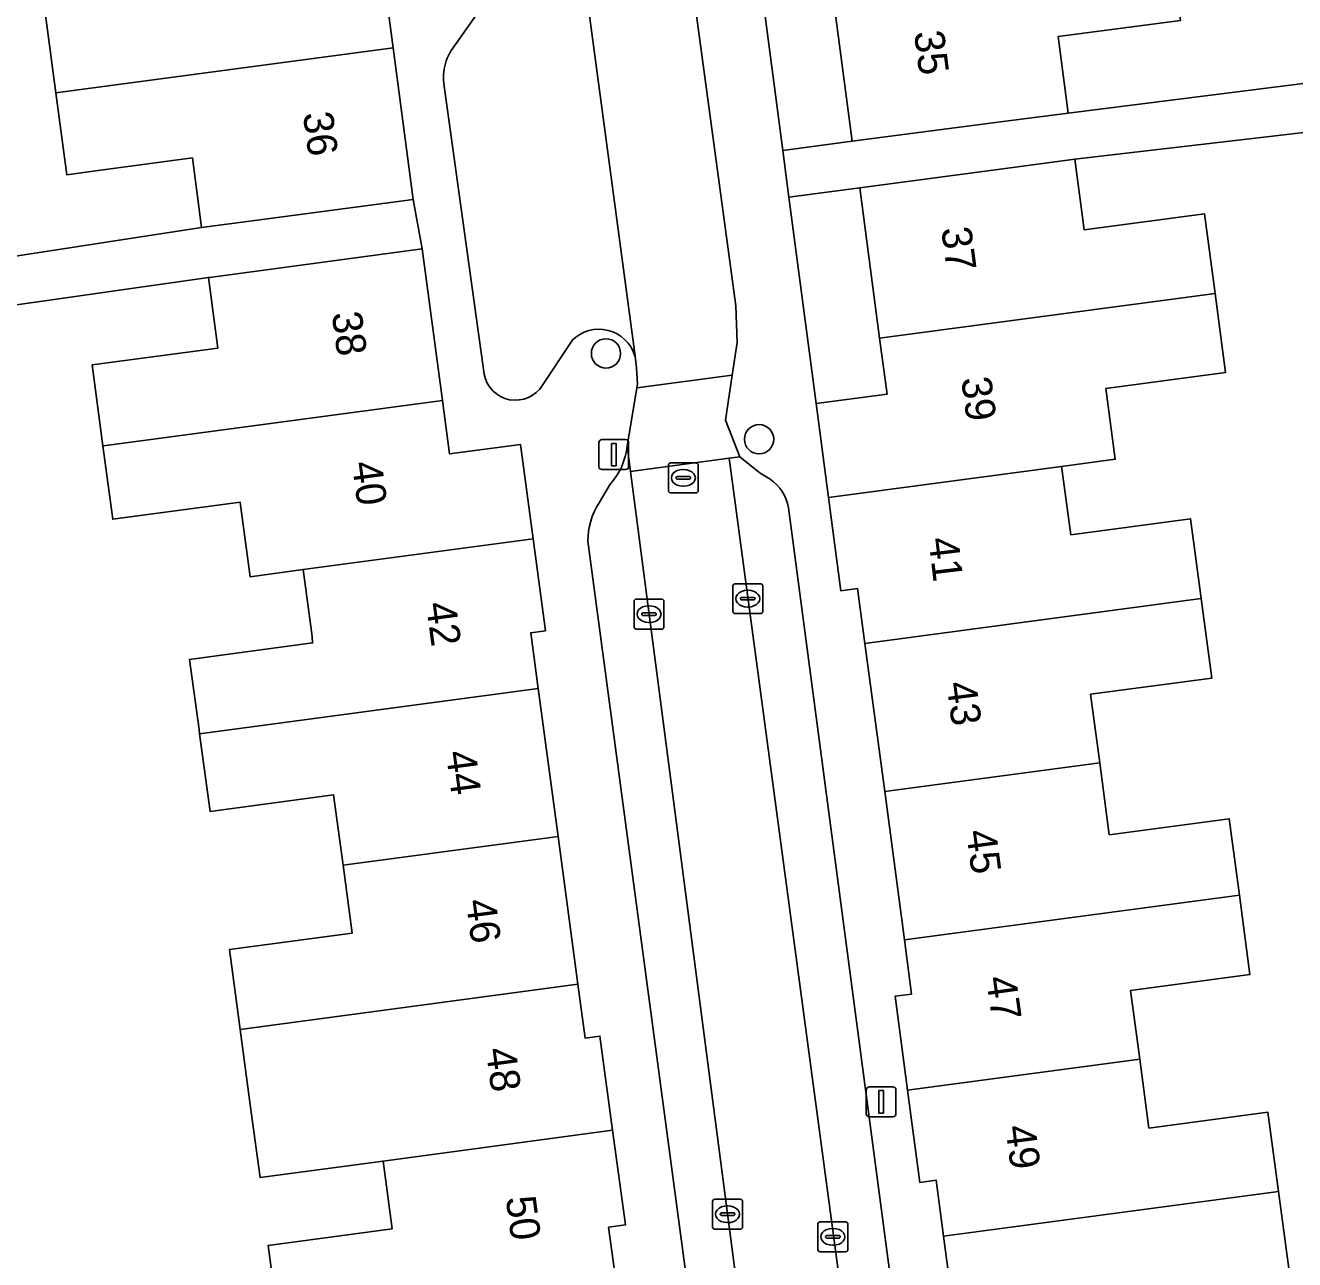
# Model space of a CAD drawing. Extents: x 163147 to 163550, y 380933 to 381639.
# Drawn here: x 163317.26 to 163359.68, y 381332.22 to 381373.46 of the extents above; entities that cross this region are included whole.
import ezdxf

# ---------------------------------------------------------------- set-up
doc = ezdxf.new("R2010")
doc.units = 0
for name, color, linetype in [('IMGEO_Boom', 7, 'Continuous'), ('IMGEO_Erf', 7, 'Continuous'), ('IMGEO_Kolk', 7, 'Continuous'), ('IMGEO_Lichtmast', 7, 'Continuous'), ('IMGEO_Pand', 7, 'Continuous'), ('IMGEO_Pand_nummerreeks', 7, 'Continuous'), ('IMGEO_Parkeervlak_open', 7, 'Continuous'), ('IMGEO_Rijbaan_lokaal_open', 7, 'Continuous'), ('IMGEO_Rioolput', 7, 'Continuous'), ('IMGEO_Voetpad_open', 7, 'Continuous')]:
    doc.layers.add(name, color=color, linetype=linetype)

msp = doc.modelspace()

# ---------------------------------------------------------------- linework, layer by layer
at = {"layer": 'IMGEO_Boom'}
for centre in [(163336.666, 381362.496), (163341.784, 381359.63)]:
    msp.add_circle(centre, 0.489, dxfattribs=at)
at = {"layer": 'IMGEO_Erf'}
for points in [[(163341.643, 381394.54), (163340.996, 381399.507), (163340.35, 381404.474), (163339.703, 381409.442), (163339.057, 381414.409), (163338.425, 381419.264), (163336.029, 381419.012), (163342.573, 381369.282), (163344.89, 381369.587), (163344.228, 381374.671), (163343.582, 381379.638), (163342.936, 381384.606), (163342.289, 381389.573)], [(163345.144, 381368.026), (163342.779, 381367.715), (163343.686, 381360.824), (163346.061, 381361.14), (163345.812, 381363.011)]]:
    msp.add_lwpolyline(points, close=True, dxfattribs=at)
for points in [[(163303.373, 381374.262), (163303.542, 381373.013), (163306.346, 381373.386), (163306.845, 381369.687), (163307.335, 381366.064), (163304.531, 381365.686), (163304.775, 381363.875), (163323.147, 381366.702), (163322.843, 381369.028), (163319.523, 381368.586), (163318.645, 381368.469), (163318.281, 381371.208), (163317.936, 381373.801)], [(163355.862, 381373.616), (163351.776, 381373.084), (163352.109, 381370.526), (163370.824, 381372.885)], [(163370.998, 381371.159), (163352.337, 381368.984), (163352.651, 381366.625), (163356.669, 381367.16), (163357.022, 381364.504), (163357.374, 381361.862), (163353.373, 381361.329), (163353.688, 381358.964), (163351.894, 381358.725), (163351.926, 381358.487), (163352.198, 381356.441), (163356.204, 381356.974), (163356.559, 381354.306), (163356.912, 381351.652), (163352.862, 381351.112), (163353.168, 381348.815), (163353.487, 381346.417), (163357.495, 381346.95), (163357.835, 381344.397), (163358.188, 381341.743), (163354.197, 381341.212), (163354.503, 381338.914), (163354.809, 381336.616), (163358.79, 381337.146), (163359.143, 381334.492), (163359.485, 381331.923)], [(163325.732, 381330.017), (163325.372, 381332.695), (163329.518, 381333.252), (163329.214, 381335.515), (163325.105, 381334.964), (163324.811, 381337.152), (163324.441, 381339.905), (163324.082, 381342.578), (163328.184, 381343.129), (163327.879, 381345.396), (163327.563, 381347.75), (163323.433, 381347.195), (163323.086, 381349.783), (163323.065, 381349.936), (163322.751, 381352.275), (163326.859, 381352.826), (163326.841, 381353.035), (163326.54, 381355.275), (163324.772, 381355.038), (163324.438, 381357.519), (163324.437, 381357.528), (163320.182, 381356.957), (163319.853, 381359.407), (163319.49, 381362.112), (163323.698, 381362.677), (163323.382, 381365.033), (163307.81, 381362.818)]]:
    msp.add_lwpolyline(points, dxfattribs=at)
at = {"layer": 'IMGEO_Kolk'}
for p, q in [((163340.905, 381353.878), (163340.905, 381354.73)), ((163340.98, 381354.804), (163341.832, 381354.804)), ((163341.393, 381354.584), (163341.418, 381354.584)), ((163341.906, 381354.73), (163341.906, 381353.878)), ((163337.603, 381353.362), (163337.603, 381354.214)), ((163337.678, 381354.288), (163338.53, 381354.288)), ((163338.091, 381354.068), (163338.116, 381354.068)), ((163338.604, 381354.214), (163338.604, 381353.362)), ((163341.164, 381354.298), (163341.164, 381354.31)), ((163341.602, 381354.261), (163341.204, 381354.261)), ((163341.207, 381354.347), (163341.605, 381354.347)), ((163341.648, 381354.31), (163341.648, 381354.298)), ((163337.862, 381353.782), (163337.862, 381353.794)), ((163338.3, 381353.745), (163337.902, 381353.745)), ((163337.905, 381353.831), (163338.303, 381353.831)), ((163338.346, 381353.794), (163338.346, 381353.782)), ((163341.832, 381353.804), (163340.98, 381353.804)), ((163341.416, 381354.024), (163341.391, 381354.024)), ((163338.53, 381353.288), (163337.678, 381353.288)), ((163338.114, 381353.508), (163338.089, 381353.508)), ((163340.228, 381333.311), (163340.228, 381334.163)), ((163340.303, 381334.237), (163341.155, 381334.237)), ((163341.229, 381334.163), (163341.229, 381333.311)), ((163340.487, 381333.731), (163340.487, 381333.743)), ((163340.925, 381333.694), (163340.527, 381333.694)), ((163340.53, 381333.78), (163340.928, 381333.78)), ((163340.716, 381334.017), (163340.741, 381334.017)), ((163340.971, 381333.743), (163340.971, 381333.731)), ((163340.739, 381333.457), (163340.714, 381333.457)), ((163343.748, 381332.556), (163343.748, 381333.408)), ((163343.823, 381333.482), (163344.675, 381333.482)), ((163344.749, 381333.408), (163344.749, 381332.556)), ((163341.155, 381333.237), (163340.303, 381333.237)), ((163344.007, 381332.976), (163344.007, 381332.988)), ((163344.445, 381332.939), (163344.047, 381332.939)), ((163344.05, 381333.025), (163344.448, 381333.025)), ((163344.236, 381333.262), (163344.261, 381333.262)), ((163344.491, 381332.988), (163344.491, 381332.976)), ((163344.675, 381332.482), (163343.823, 381332.482)), ((163344.259, 381332.702), (163344.234, 381332.702))]:
    msp.add_line(p, q, dxfattribs=at)
for points in [[(163340.905, 381353.878), (163340.905, 381354.73)], [(163340.98, 381354.804), (163341.832, 381354.804)], [(163341.906, 381354.73), (163341.906, 381353.878)], [(163337.603, 381353.362), (163337.603, 381354.214)], [(163337.678, 381354.288), (163338.53, 381354.288)], [(163338.604, 381354.214), (163338.604, 381353.362)], [(163341.832, 381353.804), (163340.98, 381353.804)], [(163338.53, 381353.288), (163337.678, 381353.288)], [(163340.228, 381333.311), (163340.228, 381334.163)], [(163340.303, 381334.237), (163341.155, 381334.237)], [(163341.229, 381334.163), (163341.229, 381333.311)], [(163343.748, 381332.556), (163343.748, 381333.408)], [(163343.823, 381333.482), (163344.675, 381333.482)], [(163344.749, 381333.408), (163344.749, 381332.556)], [(163341.155, 381333.237), (163340.303, 381333.237)], [(163344.675, 381332.482), (163343.823, 381332.482)]]:
    msp.add_lwpolyline(points, dxfattribs=at)
for centre, radius, start, end in [((163340.982, 381354.728), 0.0765, 91.552, 178.448), ((163340.982, 381354.728), 0.0765, 91.552, 178.448), ((163341.83, 381354.728), 0.0765, 1.552, 88.448), ((163341.83, 381354.728), 0.0765, 1.552, 88.448), ((163337.68, 381354.212), 0.0765, 91.552, 178.448), ((163337.68, 381354.212), 0.0765, 91.552, 178.448), ((163338.528, 381354.212), 0.0765, 1.552, 88.448), ((163338.528, 381354.212), 0.0765, 1.552, 88.448), ((163341.204, 381354.307), 0.0403, 85.8775, 175.7526), ((163341.201, 381354.297), 0.0366, 178.938, 274.7102), ((163341.605, 381354.304), 0.043, 264.8664, 352.4533), ((163341.609, 381354.309), 0.0386, 1.7309, 96.639), ((163337.902, 381353.791), 0.0403, 85.8775, 175.7526), ((163337.899, 381353.781), 0.0366, 178.938, 274.7102), ((163338.303, 381353.788), 0.043, 264.8664, 352.4533), ((163338.307, 381353.793), 0.0386, 1.7309, 96.639), ((163340.982, 381353.88), 0.0765, 181.552, 268.448), ((163340.982, 381353.88), 0.0765, 181.552, 268.448), ((163341.83, 381353.88), 0.0765, 271.552, 358.448), ((163341.83, 381353.88), 0.0765, 271.552, 358.448), ((163337.68, 381353.364), 0.0765, 181.552, 268.448), ((163337.68, 381353.364), 0.0765, 181.552, 268.448), ((163338.528, 381353.364), 0.0765, 271.552, 358.448), ((163338.528, 381353.364), 0.0765, 271.552, 358.448), ((163340.305, 381334.161), 0.0765, 91.552, 178.448), ((163340.305, 381334.161), 0.0765, 91.552, 178.448), ((163341.153, 381334.161), 0.0765, 1.552, 88.448), ((163341.153, 381334.161), 0.0765, 1.552, 88.448), ((163340.527, 381333.74), 0.0403, 85.8775, 175.7526), ((163340.524, 381333.73), 0.0366, 178.938, 274.7102), ((163340.928, 381333.737), 0.043, 264.8664, 352.4533), ((163340.932, 381333.742), 0.0386, 1.7309, 96.639), ((163340.305, 381333.313), 0.0765, 181.552, 268.448), ((163340.305, 381333.313), 0.0765, 181.552, 268.448), ((163341.153, 381333.313), 0.0765, 271.552, 358.448), ((163341.153, 381333.313), 0.0765, 271.552, 358.448), ((163343.825, 381333.406), 0.0765, 91.552, 178.448), ((163343.825, 381333.406), 0.0765, 91.552, 178.448), ((163344.673, 381333.406), 0.0765, 1.552, 88.448), ((163344.673, 381333.406), 0.0765, 1.552, 88.448), ((163344.047, 381332.985), 0.0403, 85.8775, 175.7526), ((163344.044, 381332.975), 0.0366, 178.938, 274.7102), ((163344.448, 381332.982), 0.043, 264.8664, 352.4533), ((163344.452, 381332.987), 0.0386, 1.7309, 96.639), ((163343.825, 381332.558), 0.0765, 181.552, 268.448), ((163343.825, 381332.558), 0.0765, 181.552, 268.448), ((163344.673, 381332.558), 0.0765, 271.552, 358.448), ((163344.673, 381332.558), 0.0765, 271.552, 358.448)]:
    msp.add_arc(centre, radius, start, end, dxfattribs=at)
for centre, major_axis, ratio, start_param, end_param in [((163341.392, 381354.304), (-0.387, 0.002), 0.722429, 4.712389, 7.853982), ((163341.417, 381354.304), (-0.39, 0.002), 0.717154, 1.570796, 4.712389), ((163338.09, 381353.788), (-0.387, 0.002), 0.722429, 4.712389, 7.853982), ((163338.115, 381353.788), (-0.39, 0.002), 0.717154, 1.570796, 4.712389), ((163340.715, 381333.737), (-0.387, 0.002), 0.722429, 4.712389, 7.853982), ((163340.74, 381333.737), (-0.39, 0.002), 0.717154, 1.570796, 4.712389), ((163344.235, 381332.982), (-0.387, 0.002), 0.722429, 4.712389, 7.853982), ((163344.26, 381332.982), (-0.39, 0.002), 0.717154, 1.570796, 4.712389)]:
    msp.add_ellipse(centre, major_axis=major_axis, ratio=ratio, start_param=start_param, end_param=end_param, dxfattribs=at)
at = {"layer": 'IMGEO_Lichtmast'}
for p, q in [((163336.532, 381359.617), (163337.322, 381359.617)), ((163337.322, 381359.617), (163336.532, 381359.617)), ((163336.432, 381358.717), (163336.432, 381359.517)), ((163336.432, 381359.517), (163336.432, 381358.717)), ((163337.422, 381359.517), (163337.422, 381358.717)), ((163337.422, 381358.717), (163337.422, 381359.517)), ((163337.322, 381358.617), (163336.532, 381358.617)), ((163336.532, 381358.617), (163337.322, 381358.617)), ((163345.465, 381337.993), (163346.255, 381337.993)), ((163346.255, 381337.993), (163345.465, 381337.993)), ((163345.365, 381337.093), (163345.365, 381337.893)), ((163345.365, 381337.893), (163345.365, 381337.093)), ((163346.355, 381337.893), (163346.355, 381337.093)), ((163346.355, 381337.093), (163346.355, 381337.893)), ((163346.255, 381336.993), (163345.465, 381336.993)), ((163345.465, 381336.993), (163346.255, 381336.993))]:
    msp.add_line(p, q, dxfattribs=at)
for points in [[(163336.852, 381359.492), (163337.002, 381359.492), (163337.002, 381358.742), (163336.852, 381358.742), (163336.852, 381359.492)], [(163345.785, 381337.868), (163345.935, 381337.868), (163345.935, 381337.118), (163345.785, 381337.118), (163345.785, 381337.868)]]:
    msp.add_lwpolyline(points, dxfattribs=at)
for centre, start, end in [((163336.532, 381359.517), 90, 180), ((163336.532, 381359.517), 90, 180), ((163337.322, 381359.517), 0, 90), ((163337.322, 381359.517), 360, 90), ((163336.532, 381358.717), 180, 270), ((163336.532, 381358.717), 180, 270), ((163337.322, 381358.717), 270, 0), ((163337.322, 381358.717), 270, 0), ((163345.465, 381337.893), 90, 180), ((163345.465, 381337.893), 90, 180), ((163346.255, 381337.893), 0, 90), ((163346.255, 381337.893), 360, 90), ((163345.465, 381337.093), 180, 270), ((163345.465, 381337.093), 180, 270), ((163346.255, 381337.093), 270, 0), ((163346.255, 381337.093), 270, 0)]:
    msp.add_arc(centre, 0.1, start, end, dxfattribs=at)
at = {"layer": 'IMGEO_Pand'}
for points in [[(163318.281, 381371.208), (163329.551, 381372.707), (163328.894, 381377.656), (163321.796, 381376.712), (163322.109, 381374.355), (163317.936, 381373.801)], [(163344.228, 381374.671), (163344.89, 381369.587), (163349.849, 381370.232), (163352.109, 381370.526), (163351.776, 381373.084), (163355.862, 381373.616), (163355.533, 381376.142)], [(163329.551, 381372.707), (163318.281, 381371.208), (163318.645, 381368.469), (163319.523, 381368.586), (163322.843, 381369.028), (163323.147, 381366.702), (163325.268, 381366.984), (163330.224, 381367.642)], [(163357.022, 381364.504), (163356.669, 381367.16), (163352.651, 381366.625), (163352.337, 381368.984), (163350.101, 381368.686), (163345.144, 381368.026), (163345.812, 381363.011)], [(163330.517, 381365.991), (163325.562, 381365.326), (163323.417, 381365.038), (163323.382, 381365.033), (163323.698, 381362.677), (163319.49, 381362.112), (163319.853, 381359.407), (163319.878, 381359.41), (163331.197, 381360.93)], [(163353.373, 381361.329), (163357.374, 381361.862), (163357.022, 381364.504), (163345.812, 381363.011), (163346.061, 381361.14), (163343.686, 381360.824), (163344.104, 381357.687), (163351.894, 381358.725), (163353.688, 381358.964)], [(163333.806, 381359.46), (163331.437, 381359.142), (163331.197, 381360.93), (163319.878, 381359.41), (163319.853, 381359.407), (163320.182, 381356.957), (163324.437, 381357.528), (163324.438, 381357.519), (163324.772, 381355.038), (163326.54, 381355.275), (163334.23, 381356.308)], [(163356.204, 381356.974), (163352.198, 381356.441), (163351.926, 381358.487), (163351.894, 381358.725), (163344.104, 381357.687), (163344.52, 381354.564), (163345.077, 381354.638), (163345.32, 381352.809), (163356.559, 381354.306)], [(163334.15, 381353.165), (163334.643, 381353.231), (163334.23, 381356.308), (163326.54, 381355.275), (163326.841, 381353.035), (163326.859, 381352.826), (163322.751, 381352.275), (163323.065, 381349.936), (163323.086, 381349.783), (163334.4, 381351.301)], [(163356.559, 381354.306), (163345.32, 381352.809), (163345.98, 381347.858), (163353.168, 381348.815), (163352.862, 381351.112), (163356.912, 381351.652)], [(163335.064, 381346.36), (163334.4, 381351.301), (163323.086, 381349.783), (163323.433, 381347.195), (163327.563, 381347.75), (163327.879, 381345.396)], [(163346.639, 381342.905), (163357.835, 381344.397), (163357.495, 381346.95), (163353.487, 381346.417), (163353.168, 381348.815), (163345.98, 381347.858)], [(163335.064, 381346.36), (163327.879, 381345.396), (163328.184, 381343.129), (163324.082, 381342.578), (163324.441, 381339.905), (163335.728, 381341.419)], [(163346.745, 381337.881), (163354.503, 381338.914), (163354.197, 381341.212), (163358.188, 381341.743), (163357.835, 381344.397), (163346.639, 381342.905), (163346.88, 381341.093), (163346.327, 381341.019)], [(163336.465, 381339.691), (163335.969, 381339.625), (163335.728, 381341.419), (163324.441, 381339.905), (163324.811, 381337.152), (163325.105, 381334.964), (163329.214, 381335.515), (163336.888, 381336.545)], [(163346.745, 381337.881), (163347.155, 381334.8), (163347.701, 381334.873), (163347.95, 381333.001), (163359.143, 381334.492), (163358.79, 381337.146), (163354.809, 381336.616), (163354.503, 381338.914)], [(163336.888, 381336.545), (163329.214, 381335.515), (163329.518, 381333.252), (163325.372, 381332.695), (163325.732, 381330.017), (163336.991, 381331.528), (163336.753, 381333.303), (163337.313, 381333.378)], [(163347.95, 381333.001), (163348.625, 381327.93), (163353.582, 381328.591), (163355.814, 381328.888), (163355.481, 381331.39), (163359.485, 381331.923), (163359.143, 381334.492)]]:
    msp.add_lwpolyline(points, close=True, dxfattribs=at)
at = {"layer": 'IMGEO_Parkeervlak_open'}
for points in [[(163337.636, 381362.402), (163328.901, 381427.589)], [(163335.074, 381377.714), (163331.663, 381372.853)], [(163331.263, 381371.432), (163332.592, 381361.802)], [(163334.546, 381361.438), (163335.53, 381362.932)], [(163344.364, 381305.974), (163337.483, 381358.548), (163337.371, 381359.403)], [(163342.151, 381358.294), (163341.822, 381358.499), (163341.137, 381359.042), (163340.778, 381359.002), (163347.804, 381306.716)], [(163336.804, 381358.127), (163336.434, 381357.506)], [(163346.481, 381329.237), (163342.769, 381357.339)], [(163336.06, 381356.226), (163339.515, 381330.423)]]:
    msp.add_lwpolyline(points, dxfattribs=at)
for centre, radius, start, end in [((163332.931, 381371.729), 1.694, 138.4519, 190.1052), ((163336.426, 381362.045), 1.261, 16.4479, 135.3005), ((163333.64, 381362.001), 1.067, 190.7311, 328.1642), ((163335.157, 381359.623), 2.225, 317.7581, 354.3252), ((163341.36, 381357.105), 1.428, 9.4357, 56.3797), ((163338.449, 381356.223), 2.389, 147.5079, 179.9167)]:
    msp.add_arc(centre, radius, start, end, dxfattribs=at)
at = {"layer": 'IMGEO_Rijbaan_lokaal_open'}
for points in [[(163337.636, 381362.402), (163337.687, 381362.02), (163337.718, 381361.47), (163337.698, 381361.35), (163340.886, 381361.766), (163341.054, 381362.862), (163341.003, 381364.082), (163332.34, 381428.031), (163328.901, 381427.589)], [(163341.137, 381359.042), (163340.657, 381360.272), (163340.886, 381361.766), (163337.698, 381361.35), (163337.371, 381359.403), (163337.483, 381358.548), (163340.778, 381359.002)]]:
    msp.add_lwpolyline(points, close=True, dxfattribs=at)
for points in [[(163340.778, 381359.002), (163337.483, 381358.548), (163344.364, 381305.974), (163344.476, 381305.139), (163348.087, 381305.667)], [(163347.862, 381306.29), (163347.804, 381306.716), (163340.778, 381359.002)]]:
    msp.add_lwpolyline(points, dxfattribs=at)
at = {"layer": 'IMGEO_Rioolput'}
for p, q in [((163338.75, 381357.913), (163338.75, 381358.765)), ((163338.825, 381358.839), (163339.677, 381358.839)), ((163339.751, 381358.765), (163339.751, 381357.913)), ((163339.009, 381358.333), (163339.009, 381358.345)), ((163339.447, 381358.296), (163339.049, 381358.296)), ((163339.052, 381358.382), (163339.45, 381358.382)), ((163339.238, 381358.619), (163339.263, 381358.619)), ((163339.493, 381358.345), (163339.493, 381358.333)), ((163339.261, 381358.059), (163339.236, 381358.059)), ((163339.677, 381357.839), (163338.825, 381357.839))]:
    msp.add_line(p, q, dxfattribs=at)
for points in [[(163338.75, 381357.913), (163338.75, 381358.765)], [(163338.825, 381358.839), (163339.677, 381358.839)], [(163339.751, 381358.765), (163339.751, 381357.913)], [(163339.677, 381357.839), (163338.825, 381357.839)]]:
    msp.add_lwpolyline(points, dxfattribs=at)
for centre, radius, start, end in [((163338.827, 381358.763), 0.0765, 91.552, 178.448), ((163338.827, 381358.763), 0.0765, 91.552, 178.448), ((163339.675, 381358.763), 0.0765, 1.552, 88.448), ((163339.675, 381358.763), 0.0765, 1.552, 88.448), ((163339.049, 381358.342), 0.0403, 85.8775, 175.7526), ((163339.046, 381358.332), 0.0366, 178.938, 274.7102), ((163339.45, 381358.339), 0.043, 264.8664, 352.4533), ((163339.454, 381358.344), 0.0386, 1.7309, 96.639), ((163338.827, 381357.915), 0.0765, 181.552, 268.448), ((163338.827, 381357.915), 0.0765, 181.552, 268.448), ((163339.675, 381357.915), 0.0765, 271.552, 358.448), ((163339.675, 381357.915), 0.0765, 271.552, 358.448)]:
    msp.add_arc(centre, radius, start, end, dxfattribs=at)
for centre, major_axis, ratio, start_param, end_param in [((163339.237, 381358.339), (-0.387, 0.002), 0.722429, 4.712389, 7.853982), ((163339.262, 381358.339), (-0.39, 0.002), 0.717154, 1.570796, 4.712389)]:
    msp.add_ellipse(centre, major_axis=major_axis, ratio=ratio, start_param=start_param, end_param=end_param, dxfattribs=at)
at = {"layer": 'IMGEO_Voetpad_open'}
for points in [[(163331.157, 381430.873), (163331.211, 381430.682), (163331.438, 381429.883), (163332.34, 381428.031), (163341.003, 381364.082), (163341.054, 381362.862), (163340.886, 381361.766), (163340.657, 381360.272), (163341.137, 381359.042), (163341.822, 381358.499), (163342.151, 381358.294)], [(163348.087, 381305.667), (163350.999, 381306.622), (163350.684, 381308.961), (163349.715, 381316.26), (163348.862, 381323.432), (163348.535, 381326.183), (163348.852, 381326.225), (163348.625, 381327.93), (163347.95, 381333.001), (163347.701, 381334.873), (163347.155, 381334.8), (163346.745, 381337.881), (163346.327, 381341.019), (163346.88, 381341.093), (163346.639, 381342.905), (163345.98, 381347.858), (163345.32, 381352.809), (163345.077, 381354.638), (163344.52, 381354.564), (163344.104, 381357.687), (163343.686, 381360.824), (163342.779, 381367.715), (163342.573, 381369.282), (163336.029, 381419.012)], [(163328.894, 381377.656), (163329.551, 381372.707), (163330.224, 381367.642), (163330.517, 381365.991), (163331.197, 381360.93), (163331.437, 381359.142), (163333.806, 381359.46), (163334.23, 381356.308), (163334.643, 381353.231), (163334.15, 381353.165), (163334.4, 381351.301), (163335.064, 381346.36), (163335.728, 381341.419), (163335.969, 381339.625), (163336.465, 381339.691), (163336.888, 381336.545), (163337.313, 381333.378), (163336.753, 381333.303), (163336.991, 381331.528)], [(163331.663, 381372.853), (163335.074, 381377.714)], [(163309.938, 381322.692), (163304.651, 381362.369), (163304.998, 381362.418), (163307.81, 381362.818), (163323.382, 381365.033), (163323.417, 381365.038), (163325.562, 381365.326), (163330.517, 381365.991), (163330.224, 381367.642), (163325.268, 381366.984), (163323.147, 381366.702), (163304.775, 381363.875), (163304.531, 381365.686), (163304.041, 381369.314), (163303.542, 381373.013), (163303.373, 381374.262)], [(163370.824, 381372.885), (163352.109, 381370.526), (163349.849, 381370.232), (163344.89, 381369.587), (163342.573, 381369.282), (163342.779, 381367.715), (163345.144, 381368.026), (163350.101, 381368.686), (163352.337, 381368.984), (163370.998, 381371.159)], [(163332.592, 381361.802), (163331.263, 381371.432)], [(163335.53, 381362.932), (163334.546, 381361.438)], [(163337.371, 381359.403), (163337.698, 381361.35), (163337.718, 381361.47), (163337.687, 381362.02), (163337.636, 381362.402)], [(163336.434, 381357.506), (163336.804, 381358.127)], [(163342.769, 381357.339), (163346.481, 381329.237)], [(163339.515, 381330.423), (163336.06, 381356.226)]]:
    msp.add_lwpolyline(points, dxfattribs=at)
for centre, radius, start, end in [((163332.931, 381371.729), 1.694, 138.4519, 190.1052), ((163336.426, 381362.045), 1.261, 16.4479, 135.3005), ((163333.64, 381362.001), 1.067, 190.7311, 328.1642), ((163335.157, 381359.623), 2.225, 317.7581, 354.3252), ((163341.36, 381357.105), 1.428, 9.4357, 56.3797), ((163338.449, 381356.223), 2.389, 147.5079, 179.9167)]:
    msp.add_arc(centre, radius, start, end, dxfattribs=at)

# ---------------------------------------------------------------- texts
at = {"layer": 'IMGEO_Pand_nummerreeks'}
for s, rotation, p in [('35', 277.4145, (163346.957, 381373.227)), ('36', 277.5686, (163326.534, 381370.515)), ('37', 277.5854, (163347.867, 381366.67)), ('38', 277.6545, (163327.497, 381363.839)), ('39', 277.5858, (163348.534, 381361.659)), ('40', 277.6488, (163328.17, 381358.839)), ('41', 276.7893, (163347.441, 381356.308)), ('42', 277.6488, (163330.646, 381354.138)), ('43', 277.5931, (163348.039, 381351.483)), ('44', 277.6506, (163331.311, 381349.174)), ('45', 277.5787, (163348.699, 381346.53)), ('46', 277.6506, (163331.978, 381344.213)), ('47', 278.0879, (163349.365, 381341.635)), ('48', 277.6488, (163332.646, 381339.25)), ('49', 277.5117, (163350.009, 381336.662)), ('50', 277.6506, (163333.311, 381334.289))]:
    msp.add_text(s, height=1, rotation=rotation, dxfattribs=at).set_placement(p)

doc.saveas('drawing.dxf')
